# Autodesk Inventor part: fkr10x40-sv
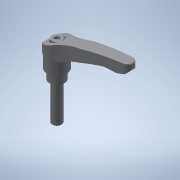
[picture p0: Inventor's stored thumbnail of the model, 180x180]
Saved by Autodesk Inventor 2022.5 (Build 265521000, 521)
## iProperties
Created: 2017-09
Part Number: fkr10x40-sv
Material: 一般
Document SubType Name: Modeling
Designer: imaocorp
Density: 1 g/cm^3
Appearance: 既定
Author: imaocorp
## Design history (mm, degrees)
node "fkr10x40-sv.x_t1"
node "fkr10x40-sv"
node "Base1"
